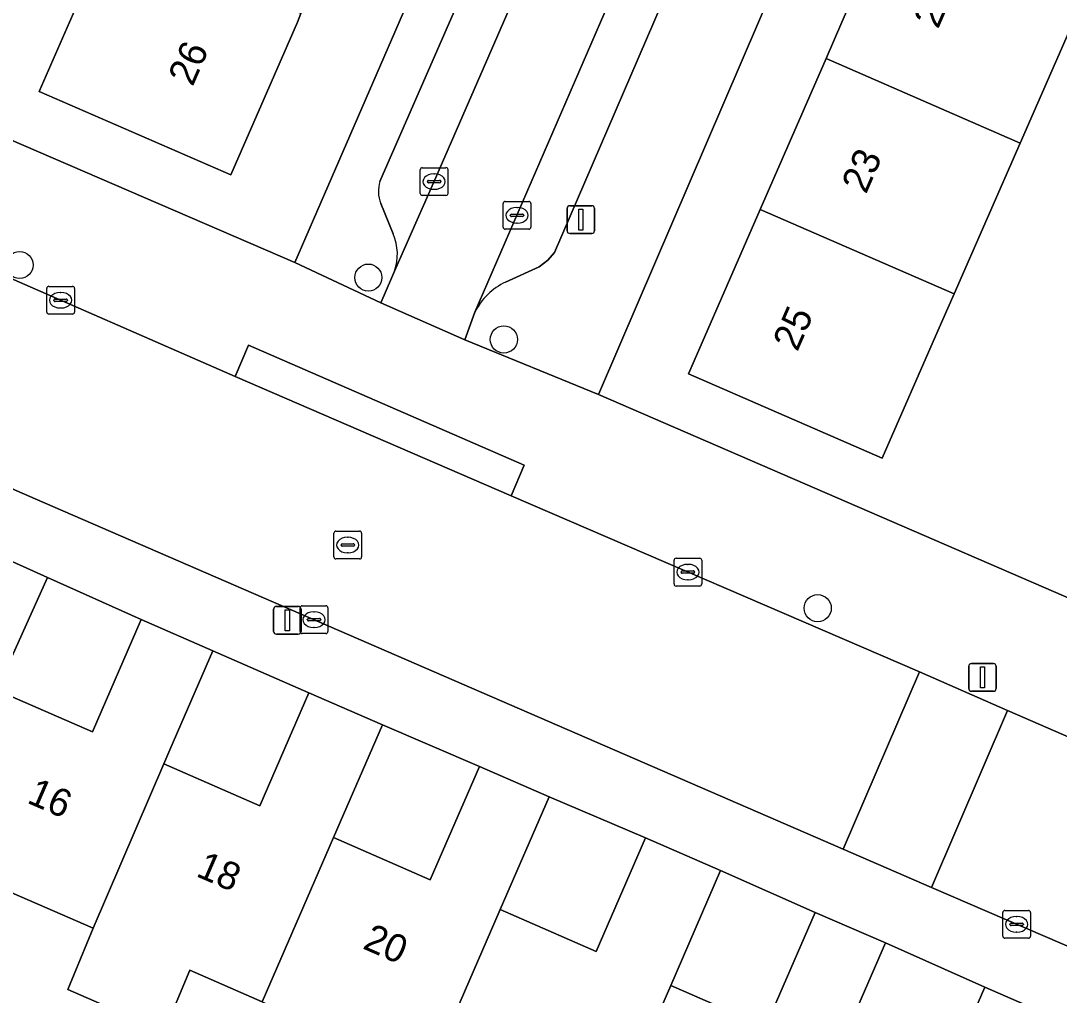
# Model space of a CAD drawing. Extents: x 162803 to 163818, y 381639 to 382475.
# Drawn here: x 163301.7 to 163339.09, y 381964.96 to 382000.04 of the extents above; entities that cross this region are included whole.
import ezdxf

# ---------------------------------------------------------------- set-up
doc = ezdxf.new("R2010")
doc.units = 0
for name, color, linetype in [('IMGEO_Boom', 7, 'Continuous'), ('IMGEO_Erf', 7, 'Continuous'), ('IMGEO_Kolk', 7, 'Continuous'), ('IMGEO_Lichtmast', 7, 'Continuous'), ('IMGEO_Pand', 7, 'Continuous'), ('IMGEO_Pand_nummerreeks', 7, 'Continuous'), ('IMGEO_Parkeervlak_open', 7, 'Continuous'), ('IMGEO_Rijbaan_lokaal_open', 7, 'Continuous'), ('IMGEO_Rioolput', 7, 'Continuous'), ('IMGEO_Voetpad_open', 7, 'Continuous')]:
    doc.layers.add(name, color=color, linetype=linetype)

msp = doc.modelspace()

# ---------------------------------------------------------------- linework, layer by layer
at = {"layer": 'IMGEO_Boom'}
for centre in [(163301.655, 381991.252), (163314.211, 381990.798), (163319.092, 381988.573), (163330.392, 381978.896)]:
    msp.add_circle(centre, 0.489, dxfattribs=at)
at = {"layer": 'IMGEO_Erf'}
for points in [[(163296.851, 382021.352), (163279.555, 382028.679), (163272.144, 382010.372), (163271.449, 382008.655), (163291.511, 382000), (163311.571, 381991.346), (163312.362, 381993.172), (163315.321, 382000), (163320.27, 382011.419), (163311.944, 382015.003), (163301.925, 382016.594), (163297.498, 382006.743), (163296.072, 382007.146), (163294.855, 382004.269), (163293.377, 382004.894), (163293.254, 382004.946), (163291.898, 382005.519), (163293.208, 382008.615), (163294.314, 382011.231), (163292.667, 382011.896)], [(163307.304, 382008.836), (163309.9, 382014.813), (163312.212, 382013.809), (163316.797, 382011.816), (163314.196, 382005.838), (163311.787, 382000.301), (163311.656, 382000), (163309.265, 381994.503), (163302.357, 381997.497), (163303.456, 382000), (163304.352, 382002.041), (163304.898, 382003.297)], [(163332.71, 381984.297), (163325.745, 381987.334), (163328.326, 381993.253), (163330.693, 381998.683), (163331.267, 382000), (163333.309, 382004.685), (163337.893, 382002.688), (163340.308, 382001.635), (163339.592, 382000), (163337.68, 381995.637), (163335.303, 381990.211), (163334.718, 381988.877)], [(163306.036, 381978.49), (163302.664, 381980.008), (163300.821, 381975.943), (163304.276, 381974.441)], [(163308.618, 381977.367), (163307.065, 381973.796), (163306.847, 381973.288), (163310.306, 381971.785), (163312.073, 381975.849)], [(163314.721, 381974.698), (163312.956, 381970.637), (163316.439, 381969.122), (163318.209, 381973.193)], [(163320.72, 381972.101), (163318.96, 381968.044), (163322.415, 381966.543), (163324.189, 381970.625)], [(163326.897, 381969.448), (163325.099, 381965.314), (163328.51, 381963.831), (163330.299, 381967.946)], [(163336.405, 381965.257), (163332.835, 381966.844), (163331.045, 381962.73), (163334.629, 381961.172)]]:
    msp.add_lwpolyline(points, close=True, dxfattribs=at)
for points in [[(163362.95, 381992.97), (163352.594, 381995.034), (163347.904, 381984.689), (163346.66, 381985.243), (163345.379, 381982.299), (163343.921, 381982.934), (163342.464, 381983.568), (163343.709, 381986.429), (163342.173, 381987.038), (163347.701, 381999.452), (163331.175, 382006.79), (163328.258, 382000), (163323.267, 381988.382), (163322.499, 381986.595), (163361.532, 381969.699)], [(163310.39, 381964.726), (163307.779, 381965.861), (163306.866, 381963.652), (163303.388, 381965.164), (163304.301, 381967.373), (163298.241, 381970.007)]]:
    msp.add_lwpolyline(points, dxfattribs=at)
at = {"layer": 'IMGEO_Kolk'}
for p, q in [((163316.154, 381994.756), (163317.006, 381994.756)), ((163316.079, 381993.83), (163316.079, 381994.682)), ((163316.567, 381994.536), (163316.592, 381994.536)), ((163317.08, 381994.682), (163317.08, 381993.83)), ((163316.338, 381994.25), (163316.338, 381994.262)), ((163316.776, 381994.213), (163316.378, 381994.213)), ((163316.381, 381994.299), (163316.779, 381994.299)), ((163316.59, 381993.976), (163316.565, 381993.976)), ((163316.822, 381994.262), (163316.822, 381994.25)), ((163317.006, 381993.756), (163316.154, 381993.756)), ((163319.065, 381992.616), (163319.065, 381993.468)), ((163319.14, 381993.542), (163319.992, 381993.542)), ((163319.553, 381993.322), (163319.578, 381993.322)), ((163320.066, 381993.468), (163320.066, 381992.616)), ((163319.324, 381993.036), (163319.324, 381993.048)), ((163319.762, 381992.999), (163319.364, 381992.999)), ((163319.367, 381993.085), (163319.765, 381993.085)), ((163319.808, 381993.048), (163319.808, 381993.036)), ((163319.992, 381992.542), (163319.14, 381992.542)), ((163319.576, 381992.762), (163319.551, 381992.762)), ((163302.632, 381989.558), (163302.632, 381990.41)), ((163302.707, 381990.484), (163303.559, 381990.484)), ((163303.12, 381990.264), (163303.145, 381990.264)), ((163303.633, 381990.41), (163303.633, 381989.558)), ((163302.891, 381989.978), (163302.891, 381989.99)), ((163303.329, 381989.941), (163302.931, 381989.941)), ((163302.934, 381990.027), (163303.332, 381990.027)), ((163303.375, 381989.99), (163303.375, 381989.978)), ((163303.559, 381989.484), (163302.707, 381989.484)), ((163303.143, 381989.704), (163303.118, 381989.704)), ((163325.218, 381979.77), (163325.218, 381980.622)), ((163325.293, 381980.696), (163326.145, 381980.696)), ((163326.219, 381980.622), (163326.219, 381979.77)), ((163325.477, 381980.19), (163325.477, 381980.202)), ((163325.915, 381980.153), (163325.517, 381980.153)), ((163325.52, 381980.239), (163325.918, 381980.239)), ((163325.706, 381980.476), (163325.731, 381980.476)), ((163325.961, 381980.202), (163325.961, 381980.19)), ((163325.729, 381979.916), (163325.704, 381979.916)), ((163326.145, 381979.696), (163325.293, 381979.696)), ((163311.756, 381978.057), (163311.756, 381978.909)), ((163311.831, 381978.983), (163312.683, 381978.983)), ((163312.244, 381978.763), (163312.269, 381978.763)), ((163312.757, 381978.909), (163312.757, 381978.057)), ((163312.015, 381978.477), (163312.015, 381978.489)), ((163312.453, 381978.44), (163312.055, 381978.44)), ((163312.058, 381978.526), (163312.456, 381978.526)), ((163312.499, 381978.489), (163312.499, 381978.477)), ((163312.683, 381977.983), (163311.831, 381977.983)), ((163312.267, 381978.203), (163312.242, 381978.203)), ((163337.055, 381967.089), (163337.055, 381967.941)), ((163337.13, 381968.015), (163337.982, 381968.015)), ((163337.543, 381967.795), (163337.568, 381967.795)), ((163338.056, 381967.941), (163338.056, 381967.089)), ((163337.314, 381967.509), (163337.314, 381967.521)), ((163337.752, 381967.472), (163337.354, 381967.472)), ((163337.357, 381967.558), (163337.755, 381967.558)), ((163337.798, 381967.521), (163337.798, 381967.509)), ((163337.566, 381967.235), (163337.541, 381967.235)), ((163337.982, 381967.015), (163337.13, 381967.015))]:
    msp.add_line(p, q, dxfattribs=at)
for points in [[(163316.154, 381994.756), (163317.006, 381994.756)], [(163316.079, 381993.83), (163316.079, 381994.682)], [(163317.08, 381994.682), (163317.08, 381993.83)], [(163317.006, 381993.756), (163316.154, 381993.756)], [(163319.065, 381992.616), (163319.065, 381993.468)], [(163319.14, 381993.542), (163319.992, 381993.542)], [(163320.066, 381993.468), (163320.066, 381992.616)], [(163319.992, 381992.542), (163319.14, 381992.542)], [(163302.632, 381989.558), (163302.632, 381990.41)], [(163302.707, 381990.484), (163303.559, 381990.484)], [(163303.633, 381990.41), (163303.633, 381989.558)], [(163303.559, 381989.484), (163302.707, 381989.484)], [(163325.218, 381979.77), (163325.218, 381980.622)], [(163325.293, 381980.696), (163326.145, 381980.696)], [(163326.219, 381980.622), (163326.219, 381979.77)], [(163326.145, 381979.696), (163325.293, 381979.696)], [(163311.756, 381978.057), (163311.756, 381978.909)], [(163311.831, 381978.983), (163312.683, 381978.983)], [(163312.757, 381978.909), (163312.757, 381978.057)], [(163312.683, 381977.983), (163311.831, 381977.983)], [(163337.055, 381967.089), (163337.055, 381967.941)], [(163337.13, 381968.015), (163337.982, 381968.015)], [(163338.056, 381967.941), (163338.056, 381967.089)], [(163337.982, 381967.015), (163337.13, 381967.015)]]:
    msp.add_lwpolyline(points, dxfattribs=at)
for centre, radius, start, end in [((163316.156, 381994.68), 0.0765, 91.552, 178.448), ((163316.156, 381994.68), 0.0765, 91.552, 178.448), ((163317.004, 381994.68), 0.0765, 1.552, 88.448), ((163317.004, 381994.68), 0.0765, 1.552, 88.448), ((163316.378, 381994.259), 0.0403, 85.8775, 175.7526), ((163316.375, 381994.249), 0.0366, 178.938, 274.7102), ((163316.779, 381994.256), 0.043, 264.8664, 352.4533), ((163316.783, 381994.261), 0.0386, 1.7309, 96.639), ((163316.156, 381993.832), 0.0765, 181.552, 268.448), ((163316.156, 381993.832), 0.0765, 181.552, 268.448), ((163317.004, 381993.832), 0.0765, 271.552, 358.448), ((163317.004, 381993.832), 0.0765, 271.552, 358.448), ((163319.142, 381993.466), 0.0765, 91.552, 178.448), ((163319.142, 381993.466), 0.0765, 91.552, 178.448), ((163319.99, 381993.466), 0.0765, 1.552, 88.448), ((163319.99, 381993.466), 0.0765, 1.552, 88.448), ((163319.364, 381993.045), 0.0403, 85.8775, 175.7526), ((163319.361, 381993.035), 0.0366, 178.938, 274.7102), ((163319.765, 381993.042), 0.043, 264.8664, 352.4533), ((163319.769, 381993.047), 0.0386, 1.7309, 96.639), ((163319.142, 381992.618), 0.0765, 181.552, 268.448), ((163319.142, 381992.618), 0.0765, 181.552, 268.448), ((163319.99, 381992.618), 0.0765, 271.552, 358.448), ((163319.99, 381992.618), 0.0765, 271.552, 358.448), ((163302.709, 381990.408), 0.0765, 91.552, 178.448), ((163302.709, 381990.408), 0.0765, 91.552, 178.448), ((163303.557, 381990.408), 0.0765, 1.552, 88.448), ((163303.557, 381990.408), 0.0765, 1.552, 88.448), ((163302.931, 381989.987), 0.0403, 85.8775, 175.7526), ((163302.928, 381989.977), 0.0366, 178.938, 274.7102), ((163303.332, 381989.984), 0.043, 264.8664, 352.4533), ((163303.336, 381989.989), 0.0386, 1.7309, 96.639), ((163302.709, 381989.56), 0.0765, 181.552, 268.448), ((163302.709, 381989.56), 0.0765, 181.552, 268.448), ((163303.557, 381989.56), 0.0765, 271.552, 358.448), ((163303.557, 381989.56), 0.0765, 271.552, 358.448), ((163325.295, 381980.62), 0.0765, 91.552, 178.448), ((163325.295, 381980.62), 0.0765, 91.552, 178.448), ((163326.143, 381980.62), 0.0765, 1.552, 88.448), ((163326.143, 381980.62), 0.0765, 1.552, 88.448), ((163325.517, 381980.199), 0.0403, 85.8775, 175.7526), ((163325.514, 381980.189), 0.0366, 178.938, 274.7102), ((163325.918, 381980.196), 0.043, 264.8664, 352.4533), ((163325.922, 381980.201), 0.0386, 1.7309, 96.639), ((163325.295, 381979.772), 0.0765, 181.552, 268.448), ((163325.295, 381979.772), 0.0765, 181.552, 268.448), ((163326.143, 381979.772), 0.0765, 271.552, 358.448), ((163326.143, 381979.772), 0.0765, 271.552, 358.448), ((163311.833, 381978.907), 0.0765, 91.552, 178.448), ((163311.833, 381978.907), 0.0765, 91.552, 178.448), ((163312.681, 381978.907), 0.0765, 1.552, 88.448), ((163312.681, 381978.907), 0.0765, 1.552, 88.448), ((163312.055, 381978.486), 0.0403, 85.8775, 175.7526), ((163312.052, 381978.476), 0.0366, 178.938, 274.7102), ((163312.456, 381978.483), 0.043, 264.8664, 352.4533), ((163312.46, 381978.488), 0.0386, 1.7309, 96.639), ((163311.833, 381978.059), 0.0765, 181.552, 268.448), ((163311.833, 381978.059), 0.0765, 181.552, 268.448), ((163312.681, 381978.059), 0.0765, 271.552, 358.448), ((163312.681, 381978.059), 0.0765, 271.552, 358.448), ((163337.132, 381967.939), 0.0765, 91.552, 178.448), ((163337.132, 381967.939), 0.0765, 91.552, 178.448), ((163337.98, 381967.939), 0.0765, 1.552, 88.448), ((163337.98, 381967.939), 0.0765, 1.552, 88.448), ((163337.354, 381967.518), 0.0403, 85.8775, 175.7526), ((163337.351, 381967.508), 0.0366, 178.938, 274.7102), ((163337.755, 381967.515), 0.043, 264.8664, 352.4533), ((163337.759, 381967.52), 0.0386, 1.7309, 96.639), ((163337.132, 381967.091), 0.0765, 181.552, 268.448), ((163337.132, 381967.091), 0.0765, 181.552, 268.448), ((163337.98, 381967.091), 0.0765, 271.552, 358.448), ((163337.98, 381967.091), 0.0765, 271.552, 358.448)]:
    msp.add_arc(centre, radius, start, end, dxfattribs=at)
for centre, major_axis, ratio, start_param, end_param in [((163316.566, 381994.256), (-0.387, 0.002), 0.722429, 4.712389, 7.853982), ((163316.591, 381994.256), (-0.39, 0.002), 0.717154, 1.570796, 4.712389), ((163319.552, 381993.042), (-0.387, 0.002), 0.722429, 4.712389, 7.853982), ((163319.577, 381993.042), (-0.39, 0.002), 0.717154, 1.570796, 4.712389), ((163303.119, 381989.984), (-0.387, 0.002), 0.722429, 4.712389, 7.853982), ((163303.144, 381989.984), (-0.39, 0.002), 0.717154, 1.570796, 4.712389), ((163325.705, 381980.196), (-0.387, 0.002), 0.722429, 4.712389, 7.853982), ((163325.73, 381980.196), (-0.39, 0.002), 0.717154, 1.570796, 4.712389), ((163312.243, 381978.483), (-0.387, 0.002), 0.722429, 4.712389, 7.853982), ((163312.268, 381978.483), (-0.39, 0.002), 0.717154, 1.570796, 4.712389), ((163337.542, 381967.515), (-0.387, 0.002), 0.722429, 4.712389, 7.853982), ((163337.567, 381967.515), (-0.39, 0.002), 0.717154, 1.570796, 4.712389)]:
    msp.add_ellipse(centre, major_axis=major_axis, ratio=ratio, start_param=start_param, end_param=end_param, dxfattribs=at)
at = {"layer": 'IMGEO_Lichtmast'}
for p, q in [((163321.367, 381992.485), (163321.367, 381993.285)), ((163321.367, 381993.285), (163321.367, 381992.485)), ((163321.467, 381993.385), (163322.257, 381993.385)), ((163322.257, 381993.385), (163321.467, 381993.385)), ((163322.357, 381993.285), (163322.357, 381992.485)), ((163322.357, 381992.485), (163322.357, 381993.285)), ((163322.257, 381992.385), (163321.467, 381992.385)), ((163321.467, 381992.385), (163322.257, 381992.385)), ((163310.8, 381978.062), (163310.8, 381978.862)), ((163310.8, 381978.862), (163310.8, 381978.062)), ((163310.9, 381978.962), (163311.69, 381978.962)), ((163311.69, 381978.962), (163310.9, 381978.962)), ((163311.79, 381978.862), (163311.79, 381978.062)), ((163311.79, 381978.062), (163311.79, 381978.862)), ((163311.69, 381977.962), (163310.9, 381977.962)), ((163310.9, 381977.962), (163311.69, 381977.962)), ((163335.829, 381976.005), (163335.829, 381976.805)), ((163335.829, 381976.805), (163335.829, 381976.005)), ((163335.929, 381976.905), (163336.719, 381976.905)), ((163336.719, 381976.905), (163335.929, 381976.905)), ((163336.819, 381976.805), (163336.819, 381976.005)), ((163336.819, 381976.005), (163336.819, 381976.805)), ((163336.719, 381975.905), (163335.929, 381975.905)), ((163335.929, 381975.905), (163336.719, 381975.905))]:
    msp.add_line(p, q, dxfattribs=at)
for points in [[(163321.787, 381993.26), (163321.937, 381993.26), (163321.937, 381992.51), (163321.787, 381992.51), (163321.787, 381993.26)], [(163311.22, 381978.837), (163311.37, 381978.837), (163311.37, 381978.087), (163311.22, 381978.087), (163311.22, 381978.837)], [(163336.249, 381976.78), (163336.399, 381976.78), (163336.399, 381976.03), (163336.249, 381976.03), (163336.249, 381976.78)]]:
    msp.add_lwpolyline(points, dxfattribs=at)
for centre, start, end in [((163321.467, 381993.285), 90, 180), ((163321.467, 381993.285), 90, 180), ((163322.257, 381993.285), 0, 90), ((163322.257, 381993.285), 360, 90), ((163321.467, 381992.485), 180, 270), ((163321.467, 381992.485), 180, 270), ((163322.257, 381992.485), 270, 0), ((163322.257, 381992.485), 270, 0), ((163310.9, 381978.862), 90, 180), ((163310.9, 381978.862), 90, 180), ((163311.69, 381978.862), 0, 90), ((163311.69, 381978.862), 360, 90), ((163310.9, 381978.062), 180, 270), ((163310.9, 381978.062), 180, 270), ((163311.69, 381978.062), 270, 0), ((163311.69, 381978.062), 270, 0), ((163335.929, 381976.805), 90, 180), ((163335.929, 381976.805), 90, 180), ((163336.719, 381976.805), 0, 90), ((163336.719, 381976.805), 360, 90), ((163335.929, 381976.005), 180, 270), ((163335.929, 381976.005), 180, 270), ((163336.719, 381976.005), 270, 0), ((163336.719, 381976.005), 270, 0)]:
    msp.add_arc(centre, 0.1, start, end, dxfattribs=at)
at = {"layer": 'IMGEO_Pand'}
for points in [[(163337.68, 381995.637), (163339.592, 382000), (163340.308, 382001.635), (163337.893, 382002.688), (163333.309, 382004.685), (163331.267, 382000), (163330.693, 381998.683)], [(163304.898, 382003.297), (163304.352, 382002.041), (163303.456, 382000), (163302.357, 381997.497), (163309.265, 381994.503), (163311.656, 382000), (163311.787, 382000.301)], [(163337.68, 381995.637), (163330.693, 381998.683), (163328.326, 381993.253), (163335.303, 381990.211)], [(163328.326, 381993.253), (163325.745, 381987.334), (163332.71, 381984.297), (163334.718, 381988.877), (163335.303, 381990.211)], [(163306.847, 381973.288), (163307.065, 381973.796), (163308.618, 381977.367), (163306.036, 381978.49), (163304.276, 381974.441), (163300.821, 381975.943), (163298.824, 381971.348), (163298.241, 381970.007), (163304.301, 381967.373)], [(163310.39, 381964.726), (163312.956, 381970.637), (163314.721, 381974.698), (163312.073, 381975.849), (163310.306, 381971.785), (163306.847, 381973.288), (163304.301, 381967.373), (163303.388, 381965.164), (163306.866, 381963.652), (163307.779, 381965.861)], [(163320.72, 381972.101), (163318.209, 381973.193), (163316.439, 381969.122), (163312.956, 381970.637), (163310.39, 381964.726), (163313.396, 381963.42), (163312.152, 381960.558), (163315.144, 381959.258), (163316.388, 381962.119), (163318.96, 381968.044)], [(163322.55, 381959.44), (163325.099, 381965.314), (163326.897, 381969.448), (163324.189, 381970.625), (163322.415, 381966.543), (163318.96, 381968.044), (163316.388, 381962.119)], [(163331.045, 381962.73), (163332.835, 381966.844), (163330.299, 381967.946), (163328.51, 381963.831), (163325.099, 381965.314), (163322.55, 381959.44), (163321.719, 381957.526), (163327.66, 381954.948), (163328.491, 381956.858)], [(163338.923, 381964.162), (163336.405, 381965.257), (163334.629, 381961.172), (163331.045, 381962.73), (163328.491, 381956.858), (163334.594, 381954.205), (163337.185, 381960.16)]]:
    msp.add_lwpolyline(points, close=True, dxfattribs=at)
at = {"layer": 'IMGEO_Parkeervlak_open'}
for points in [[(163328.825, 382010.047), (163333.345, 382020.461), (163331.738, 382021.158), (163322.577, 382000), (163318.052, 381989.55)], [(163315.149, 381991.029), (163316.562, 381994.209), (163319.078, 382000), (163321.729, 382006.103), (163323.733, 382010.699)], [(163320.889, 382008.583), (163317.138, 382000), (163314.63, 381994.261)], [(163319.153, 381990.64), (163320.362, 381991.187), (163320.672, 381991.422), (163320.911, 381991.698), (163324.487, 382000), (163326.904, 382005.61), (163326.975, 382006.022), (163326.947, 382006.371), (163326.461, 382007.544)], [(163314.663, 381993.47), (163315.109, 381992.372)]]:
    msp.add_lwpolyline(points, dxfattribs=at)
for centre, radius, start, end in [((163315.705, 381993.91), 1.131, 161.8996, 202.8783), ((163313.417, 381991.65), 1.84, 340.2878, 23.1242), ((163320.148, 381988.534), 2.329, 115.2879, 154.1368)]:
    msp.add_arc(centre, radius, start, end, dxfattribs=at)
at = {"layer": 'IMGEO_Rijbaan_lokaal_open'}
for points in [[(163331.738, 382021.158), (163328.767, 382022.447), (163328.165, 382021.067), (163323.733, 382010.699), (163321.729, 382006.103), (163319.078, 382000), (163316.562, 381994.209), (163315.149, 381991.029), (163315.04, 381990.784), (163314.664, 381989.892), (163317.691, 381988.56), (163318.052, 381989.55), (163322.577, 382000)], [(163298.707, 381984.363), (163302.214, 381982.84), (163331.307, 381970.219), (163334.063, 381976.602), (163319.351, 381982.939), (163309.414, 381987.243), (163300.295, 381991.223), (163297.541, 381984.881)], [(163334.063, 381976.602), (163331.307, 381970.219), (163334.486, 381968.838), (163337.225, 381975.21)], [(163360.196, 381965.225), (163337.225, 381975.21), (163334.486, 381968.838), (163345.294, 381964.18), (163357.753, 381958.749), (163359.789, 381957.922), (163393.809, 381943.083), (163396.507, 381949.508), (163370.112, 381960.939)]]:
    msp.add_lwpolyline(points, close=True, dxfattribs=at)
at = {"layer": 'IMGEO_Rioolput'}
for p, q in [((163313.044, 381981.67), (163313.896, 381981.67)), ((163312.969, 381980.744), (163312.969, 381981.596)), ((163313.457, 381981.45), (163313.482, 381981.45)), ((163313.97, 381981.596), (163313.97, 381980.744)), ((163313.228, 381981.164), (163313.228, 381981.176)), ((163313.666, 381981.127), (163313.268, 381981.127)), ((163313.271, 381981.213), (163313.669, 381981.213)), ((163313.48, 381980.89), (163313.455, 381980.89)), ((163313.712, 381981.176), (163313.712, 381981.164)), ((163313.896, 381980.67), (163313.044, 381980.67))]:
    msp.add_line(p, q, dxfattribs=at)
for points in [[(163313.044, 381981.67), (163313.896, 381981.67)], [(163312.969, 381980.744), (163312.969, 381981.596)], [(163313.97, 381981.596), (163313.97, 381980.744)], [(163313.896, 381980.67), (163313.044, 381980.67)]]:
    msp.add_lwpolyline(points, dxfattribs=at)
for centre, radius, start, end in [((163313.046, 381981.594), 0.0765, 91.552, 178.448), ((163313.046, 381981.594), 0.0765, 91.552, 178.448), ((163313.894, 381981.594), 0.0765, 1.552, 88.448), ((163313.894, 381981.594), 0.0765, 1.552, 88.448), ((163313.268, 381981.173), 0.0403, 85.8775, 175.7526), ((163313.265, 381981.163), 0.0366, 178.938, 274.7102), ((163313.669, 381981.17), 0.043, 264.8664, 352.4533), ((163313.673, 381981.175), 0.0386, 1.7309, 96.639), ((163313.046, 381980.746), 0.0765, 181.552, 268.448), ((163313.046, 381980.746), 0.0765, 181.552, 268.448), ((163313.894, 381980.746), 0.0765, 271.552, 358.448), ((163313.894, 381980.746), 0.0765, 271.552, 358.448)]:
    msp.add_arc(centre, radius, start, end, dxfattribs=at)
for centre, major_axis, ratio, start_param, end_param in [((163313.456, 381981.17), (-0.387, 0.002), 0.722429, 4.712389, 7.853982), ((163313.481, 381981.17), (-0.39, 0.002), 0.717154, 1.570796, 4.712389)]:
    msp.add_ellipse(centre, major_axis=major_axis, ratio=ratio, start_param=start_param, end_param=end_param, dxfattribs=at)
at = {"layer": 'IMGEO_Voetpad_open'}
for points in [[(163323.733, 382010.699), (163328.165, 382021.067), (163328.767, 382022.447), (163334.915, 382036.546), (163340.935, 382050.494), (163346.757, 382063.88), (163349.1, 382069.351), (163347.746, 382069.96), (163322.712, 382012.16), (163320.918, 382012.914), (163320.27, 382011.419), (163315.321, 382000), (163312.362, 381993.172), (163311.571, 381991.346), (163314.664, 381989.892), (163315.04, 381990.784), (163315.149, 381991.029)], [(163318.052, 381989.55), (163317.691, 381988.56), (163322.499, 381986.595), (163323.267, 381988.382), (163328.258, 382000), (163331.175, 382006.79), (163331.551, 382007.665), (163331.655, 382007.908), (163329.868, 382008.632), (163355.059, 382066.816)], [(163161.734, 382044.254), (163197.135, 382032.623), (163200.444, 382031.53), (163208.637, 382028.823), (163209.414, 382028.496), (163209.865, 382029.593), (163221.055, 382025.109), (163220.636, 382023.993), (163241.137, 382015.775), (163244.386, 382014.495), (163257.778, 382009.046), (163258.164, 382010.136), (163269.369, 382005.691), (163268.89, 382004.622), (163276.65, 382001.485), (163297.139, 381992.593), (163300.295, 381991.223), (163309.414, 381987.243), (163309.902, 381988.367), (163319.822, 381984.046), (163319.351, 381982.939), (163334.063, 381976.602), (163337.225, 381975.21), (163360.196, 381965.225)], [(163361.532, 381969.699), (163322.499, 381986.595), (163317.691, 381988.56), (163314.664, 381989.892), (163311.571, 381991.346), (163291.511, 382000), (163271.449, 382008.655), (163266.604, 382010.447), (163263.485, 382011.703), (163260.414, 382012.994), (163257.35, 382014.223), (163234.283, 382023.476), (163223.089, 382027.966)], [(163314.63, 381994.261), (163317.138, 382000), (163320.889, 382008.583)], [(163326.461, 382007.544), (163326.947, 382006.371), (163326.975, 382006.022), (163326.904, 382005.61), (163324.487, 382000), (163320.911, 381991.698), (163320.672, 381991.422), (163320.362, 381991.187), (163319.153, 381990.64)], [(163315.109, 381992.372), (163314.663, 381993.47)], [(163302.214, 381982.84), (163298.707, 381984.363), (163297.541, 381984.881), (163294.397, 381986.278), (163283.065, 381991.169)], [(163278.579, 381990.44), (163281.713, 381989.031), (163297.883, 381982.108), (163301.045, 381980.736), (163302.664, 381980.008), (163306.036, 381978.49), (163308.618, 381977.367), (163312.073, 381975.849), (163314.721, 381974.698), (163318.209, 381973.193), (163320.72, 381972.101), (163324.189, 381970.625), (163326.897, 381969.448), (163330.299, 381967.946), (163332.835, 381966.844), (163336.405, 381965.257), (163338.923, 381964.162), (163342.419, 381962.629), (163345.145, 381961.444), (163347.42, 381960.503)], [(163345.294, 381964.18), (163334.486, 381968.838), (163331.307, 381970.219), (163302.214, 381982.84)], [(163300.821, 381975.943), (163302.664, 381980.008), (163301.045, 381980.736)]]:
    msp.add_lwpolyline(points, dxfattribs=at)
msp.add_lwpolyline([(163319.822, 381984.046), (163309.902, 381988.367), (163309.414, 381987.243), (163319.351, 381982.939)], close=True, dxfattribs=at)
for centre, radius, start, end in [((163315.705, 381993.91), 1.131, 161.8996, 202.8783), ((163313.417, 381991.65), 1.84, 340.2878, 23.1242), ((163320.148, 381988.534), 2.329, 115.2879, 154.1368)]:
    msp.add_arc(centre, radius, start, end, dxfattribs=at)

# ---------------------------------------------------------------- texts
at = {"layer": 'IMGEO_Pand_nummerreeks'}
for s, rotation, p in [('21', 66.4498, (163334.723, 381999.72)), ('26', 66.4924, (163307.886, 381997.65)), ('23', 66.4435, (163332.132, 381993.778)), ('25', 66.4435, (163329.658, 381988.103)), ('16', 336.5335, (163301.883, 381971.906)), ('18', 336.5335, (163307.969, 381969.264)), ('20', 336.5316, (163313.97, 381966.659))]:
    msp.add_text(s, height=1, rotation=rotation, dxfattribs=at).set_placement(p)

doc.saveas('drawing.dxf')
